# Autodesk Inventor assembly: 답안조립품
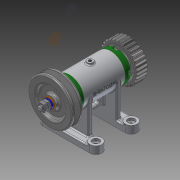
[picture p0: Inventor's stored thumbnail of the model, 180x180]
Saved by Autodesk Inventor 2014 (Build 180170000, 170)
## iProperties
Created: 2015-11
Part Number: 답안조립품
Document SubType Name: Assembly
Designer: SEC
Author: SEC
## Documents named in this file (13)
- C:\Users\SEC\Desktop\451109V1001\답안조립품.iam
- C:\Users\SEC\Desktop\451109V1001\1본체.ipt
- C:\Users\SEC\Desktop\451109V1001\커버.ipt
- C:\Users\SEC\Desktop\451109V1001\베어링 15 x 32 x 9.ipt
- C:\Users\SEC\Desktop\451109V1001\축.ipt
- C:\Users\SEC\Desktop\451109V1001\오일 실 15 25 7.ipt
- C:\Users\SEC\Desktop\451109V1001\볼트 M4 x 12.ipt
- C:\Users\SEC\Desktop\451109V1001\키 3 x 3 x 12.ipt
- C:\Users\SEC\Desktop\451109V1001\V벨트풀리.ipt
- C:\Users\SEC\Desktop\451109V1001\스퍼기어.ipt
- C:\Users\SEC\Desktop\451109V1001\와셔 8x17.ipt
- C:\Users\SEC\Desktop\451109V1001\스프링와셔 8.ipt
- C:\Users\SEC\Desktop\451109V1001\너트 M 8.ipt
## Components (12 placed, 4 different names)
1. 1본체:1
2. KS B 2023 6002 - 15 x 32 x 9:1
3. KS B 2023 6002 - 15 x 32 x 9:2
4. V벨트풀리:1 — 각도:3
5. ISO 4762 M4 x 12:1
6. ISO 4762 M4 x 12:3
7. ISO 4762 M4 x 12:4
8. ISO 4762 M4 x 12:5
9. ISO 4762 M4 x 12:2
10. ISO 4762 M4 x 12:6
11. ISO 4762 M4 x 12:7
12. ISO 4762 M4 x 12:8
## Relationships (1: Angle 1)
- 각도:3 [Angle]: V벨트풀리:1
